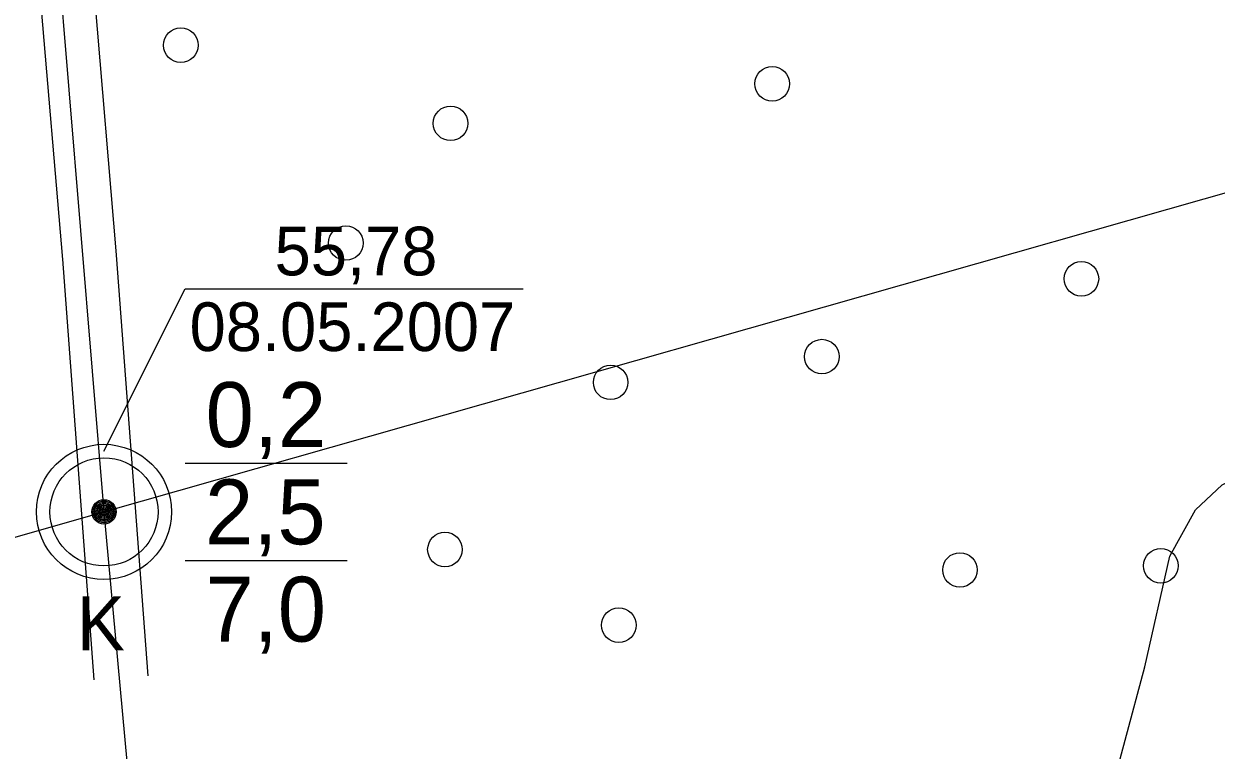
# Model space of a CAD drawing. Extents: x 532503 to 539665, y 6557663 to 6561526.
# Drawn here: x 534702 to 534790.2, y 6559745.4 to 6559799.2 of the extents above; entities that cross this region are included whole.
import ezdxf

# ---------------------------------------------------------------- set-up
doc = ezdxf.new("R2010")
doc.units = 0
for name, color, linetype in [('GEOLPUNKT', 7, 'Continuous'), ('HALJASTUS', 7, 'Continuous'), ('HORISONTAAL-EH2000', 7, 'Continuous'), ('Lõige', 7, 'Continuous'), ('Proovid', 7, 'Continuous'), ('TEE', 7, 'Continuous'), ('Veetase', 7, 'Continuous')]:
    doc.layers.add(name, color=color, linetype=linetype)

# ---------------------------------------------------------------- blocks, each defined once
blk = doc.blocks.new('METS')
at = {"layer": 'HALJASTUS'}
blk.add_circle((0, 0), 0.8, dxfattribs=at)

msp = doc.modelspace()

# ---------------------------------------------------------------- linework, layer by layer
at = {"layer": 'GEOLPUNKT'}
for p, q in [((534713.91, 6559766.66), (534725.91, 6559766.66)), ((534713.91, 6559759.46), (534725.91, 6559759.46))]:
    msp.add_line(p, q, dxfattribs=at)
for radius in [5, 4, 0.9, 0.801, 0.7, 0.6, 0.5, 0.4, 0.3, 0.2, 0.1]:
    msp.add_circle((534707.91, 6559763.06), radius, dxfattribs=at)
at = {"layer": 'HORISONTAAL-EH2000'}
msp.add_lwpolyline([(534782.011, 6559740.744), (534784.918, 6559751.603), (534786.772, 6559759.781), (534788.664, 6559763.22), (534790.626, 6559765.06), (534795.645, 6559767.649), (534801.292, 6559769.209), (534812.526, 6559771.015), (534825.875, 6559774.44)], dxfattribs=at)
at = {"layer": 'Lõige'}
for points in [[(534686.418, 6560054.502), (534688.17, 6560025.47), (534697.52, 6559887.983), (534707.91, 6559763.06), (534733.5, 6559485.14), (534735.537, 6559463.016)], [(533917.426, 6559650.435), (533949.04, 6559659.85), (534215.74, 6559786.31), (534470.46, 6559695.5), (534707.91, 6559763.06), (534929.16, 6559826.01), (535198.18, 6559814.49), (535305.655, 6559887.851), (535520.8, 6559960.87), (535543.919, 6559970.997)]]:
    msp.add_lwpolyline(points, dxfattribs=at)
at = {"layer": 'TEE'}
for p, q in [((534704.856, 6559781.73), (534702.051, 6559814.744)), ((534708.841, 6559782.069), (534706.036, 6559815.083)), ((534707.193, 6559750.622), (534704.854, 6559781.749)), ((534711.182, 6559750.922), (534708.843, 6559782.049))]:
    msp.add_line(p, q, dxfattribs=at)
at = {"layer": 'Veetase'}
for p, q in [((534707.91, 6559767.56), (534713.91, 6559779.56)), ((534713.91, 6559779.56), (534738.91, 6559779.56))]:
    msp.add_line(p, q, dxfattribs=at)

# ---------------------------------------------------------------- block references
at = {"layer": 'HALJASTUS', "xscale": 1.6, "yscale": 1.6000000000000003}
for p in [(534713.592, 6559797.591), (534757.346, 6559794.735), (534733.553, 6559791.81), (534725.805, 6559782.954), (534780.22, 6559780.307), (534761.02, 6559774.548), (534745.394, 6559772.643), (534733.135, 6559760.271), (534771.239, 6559758.76), (534786.098, 6559759.073), (534745.995, 6559754.676)]:
    msp.add_blockref('METS', p, dxfattribs=at)

# ---------------------------------------------------------------- texts
at = {"layer": 'GEOLPUNKT'}
for s, p in [('0,2', (534715.428, 6559767.86)), ('2,5', (534715.384, 6559760.66)), ('7,0', (534715.412, 6559753.46))]:
    msp.add_text(s, height=4.8, dxfattribs=at).set_placement(p)
at = {"layer": 'Proovid'}
msp.add_text('K', height=4, dxfattribs=at).set_placement((534705.888, 6559752.808))
at = {"layer": 'Veetase'}
for s, p in [('55,78', (534720.531, 6559780.56)), ('08.05.2007', (534714.243, 6559774.96))]:
    msp.add_text(s, height=3.6, dxfattribs=at).set_placement(p)

doc.saveas('drawing.dxf')
